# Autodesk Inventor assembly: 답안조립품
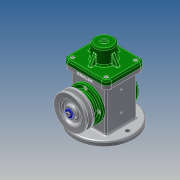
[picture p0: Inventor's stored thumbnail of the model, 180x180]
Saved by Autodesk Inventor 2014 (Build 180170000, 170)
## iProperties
Created: 2018-10
Part Number: 답안조립품
Document SubType Name: Assembly
Designer: kb542
Author: kb542
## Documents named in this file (18)
- C:\Users\kb542\Desktop\481007V1001\답안조립품.iam
- C:\Users\kb542\Desktop\481007V1001\본체.ipt
- C:\Users\kb542\Desktop\481007V1001\편심축.ipt
- C:\Users\kb542\Desktop\481007V1001\E-링.ipt
- C:\Users\kb542\Desktop\481007V1001\V-벨트풀리.ipt
- C:\Users\kb542\Desktop\481007V1001\덮개.ipt
- C:\Users\kb542\Desktop\481007V1001\뒤커버.ipt
- C:\Users\kb542\Desktop\481007V1001\링크.ipt
- C:\Users\kb542\Desktop\481007V1001\베어링 17 x 40 x 12.ipt
- C:\Users\kb542\Desktop\481007V1001\볼트 M4 x 8.ipt
- C:\Users\kb542\Desktop\481007V1001\볼트 M4 x 10.ipt
- C:\Users\kb542\Desktop\481007V1001\슬라이더.ipt
- C:\Users\kb542\Desktop\481007V1001\앞커버.ipt
- C:\Users\kb542\Desktop\481007V1001\오일 실 17 30 8.ipt
- C:\Users\kb542\Desktop\481007V1001\와셔 4x16.ipt
- C:\Users\kb542\Desktop\481007V1001\클레비스 핀 6 x 22.ipt
- 클레비스 핀 6 x 22.ipt
- C:\Users\kb542\Desktop\481007V1001\키 4 x 4 x 12.ipt
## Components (2 placed, 2 different names)
1. E-링:1
2. V-벨트풀리:1
